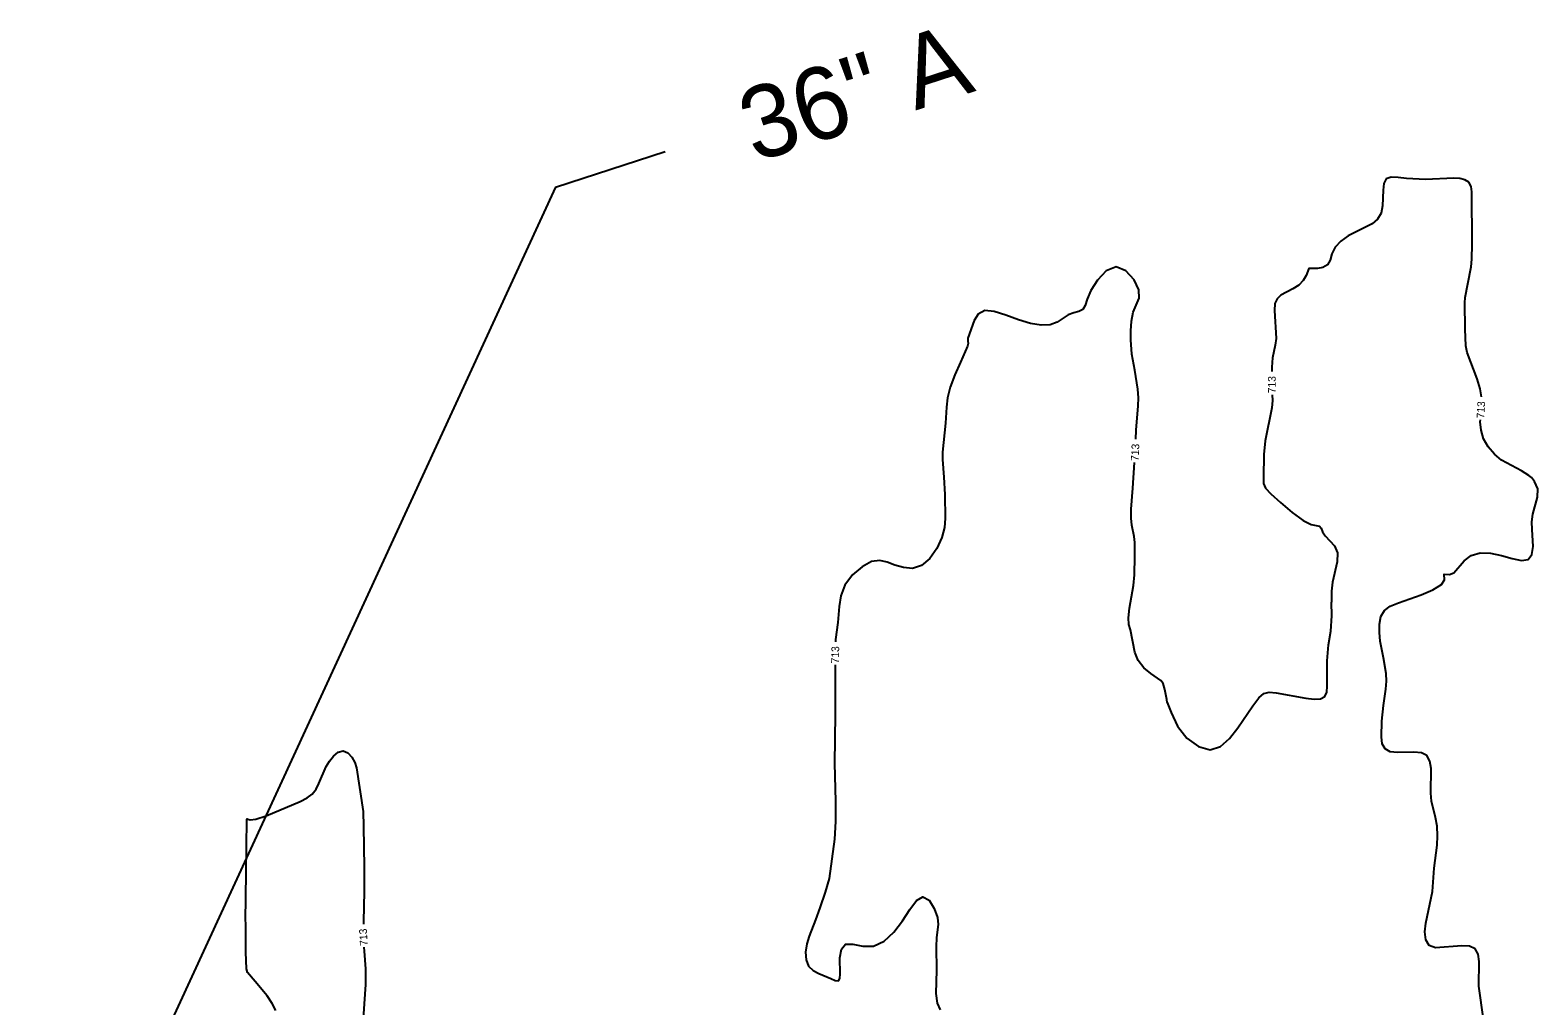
# Model space of a CAD drawing. Extents: x -468548933 to 3387700, y -306089263 to 1207014.
# Drawn here: x 1838088 to 1838869, y 536656 to 537162 of the extents above; entities that cross this region are included whole.
import ezdxf

# ---------------------------------------------------------------- set-up
doc = ezdxf.new("R2010")
doc.units = 0
for name, color, linetype in [('DT_X_Contour_Minor', 7, 'Continuous'), ('Level 19', 7, 'Continuous'), ('Level 40', 7, 'Continuous')]:
    doc.layers.add(name, color=color, linetype=linetype)

msp = doc.modelspace()

# ---------------------------------------------------------------- linework, layer by layer
at = {"layer": 'DT_X_Contour_Minor'}
for points in [[(1838839.34, 536971.92), (1838838.75, 536976.14), (1838837.15, 536981.31), (1838831.89, 536994.94), (1838831.25, 536998.25), (1838830.85, 537006.92), (1838830.82, 537020.53), (1838830.99, 537023.45), (1838832.27, 537030.52), (1838834.02, 537039.35), (1838834.42, 537043.28), (1838834.48, 537050.97), (1838834.37, 537078.09), (1838833.96, 537080.88), (1838832.86, 537083.05), (1838830.82, 537084.39), (1838828.1, 537085.01), (1838825.06, 537085.14), (1838810.3, 537084.43), (1838800.61, 537085.08), (1838796.18, 537085.6), (1838792.52, 537085.71), (1838789.97, 537084.79), (1838788.74, 537082.43), (1838788.4, 537078.97), (1838788.16, 537070.88), (1838787.34, 537067.09), (1838785.61, 537063.93), (1838782.76, 537061.56), (1838770.41, 537055.41), (1838766.48, 537052.64), (1838763.56, 537049.47), (1838761.96, 537046.03), (1838760.98, 537042.79), (1838759.63, 537040.29), (1838757.24, 537038.93), (1838754.38, 537038.42), (1838750, 537038.35), (1838748.5, 537034.72), (1838747.04, 537032.2), (1838744.8, 537029.74), (1838741.76, 537027.79), (1838735.52, 537024.59), (1838733.52, 537022.73), (1838732.44, 537020.22), (1838732.13, 537016.69), (1838733, 537002.19), (1838732.61, 536998.7), (1838731.16, 536992.1), (1838730.77, 536987.33), (1838730.78, 536984.98)], [(1838660.32, 536949.9), (1838660.54, 536954.7), (1838661.62, 536967.33), (1838661.72, 536971.45), (1838661.46, 536975.87), (1838659.78, 536985.71), (1838658.27, 536994.07), (1838657.74, 537001.5), (1838657.71, 537006.18), (1838658.04, 537011.16), (1838659.03, 537015.75), (1838662.11, 537023.07), (1838662, 537027.28), (1838659.52, 537032.51), (1838655.24, 537037.18), (1838650.1, 537039.2), (1838644.96, 537037.17), (1838640.44, 537032.42), (1838637.09, 537026.96), (1838635.21, 537022.47), (1838634.13, 537019.23), (1838632.92, 537017.16), (1838630.89, 537016.09), (1838628.23, 537015.43), (1838625.39, 537014.44), (1838619.7, 537010.67), (1838616.04, 537009.24), (1838611.34, 537009.02), (1838605.74, 537009.94), (1838599.55, 537011.78), (1838593.11, 537014.17), (1838587.08, 537016.14), (1838582.13, 537016.56), (1838578.78, 537014.7), (1838576.7, 537011.43), (1838573.43, 537002.38), (1838573.37, 537000.72), (1838573.58, 536999.53), (1838573.2, 536998.14), (1838569.53, 536989.88), (1838566.69, 536983.38), (1838564.26, 536976.87), (1838562.89, 536971.33), (1838562.33, 536966.63), (1838561.78, 536958.25), (1838560.26, 536943.26), (1838560.22, 536939.36), (1838560.89, 536930.24), (1838561.49, 536921.31), (1838561.65, 536908.82), (1838561.23, 536904.16), (1838559.91, 536898.99), (1838557.35, 536893.36), (1838553.74, 536888.15), (1838549.42, 536884.45), (1838544.72, 536883.04), (1838539.97, 536883.42), (1838535.54, 536884.77), (1838531.61, 536886.27), (1838527.79, 536887.12), (1838523.53, 536886.52), (1838518.55, 536883.91), (1838513.59, 536879.66), (1838509.67, 536874.41), (1838507.5, 536868.76), (1838506.65, 536863.29), (1838506.06, 536854.99), (1838504.84, 536846.15), (1838504.81, 536845.01)], [(1838730.99, 536972.98), (1838731.12, 536969.94), (1838730.76, 536966.25), (1838727.36, 536949.09), (1838726.72, 536942.01), (1838726.42, 536930.13), (1838726.51, 536926.93), (1838727.48, 536924.64), (1838730.22, 536921.71), (1838735.23, 536917.12), (1838741.37, 536911.95), (1838747.11, 536907.81), (1838751.25, 536905.83), (1838755.41, 536904.93), (1838756.28, 536903.84), (1838757.1, 536902.05), (1838758.49, 536899.87), (1838763.26, 536894.66), (1838764.77, 536891.02), (1838764.62, 536886.36), (1838762.23, 536875.91), (1838761.72, 536871.16), (1838761.78, 536865.57)], [(1838865.3, 536930.15), (1838863.89, 536931.22), (1838860.18, 536933.61), (1838849.7, 536939.15), (1838846.13, 536942.17), (1838842.87, 536945.96), (1838840.42, 536950.2), (1838839.13, 536954.61), (1838838.77, 536959.02), (1838838.81, 536959.93)], [(1838676.54, 536813.6), (1838676.4, 536815.05), (1838675.4, 536820.33), (1838674.47, 536823.39), (1838673.26, 536825.01), (1838668.05, 536828.51), (1838664.49, 536831.49), (1838661.52, 536835.27), (1838659.84, 536839.7), (1838657.61, 536851.2), (1838656.79, 536853.98), (1838656.49, 536857.47), (1838657.03, 536862.35), (1838659.09, 536874.17), (1838659.67, 536879.75), (1838659.91, 536889.22), (1838659.79, 536896.53), (1838659.48, 536899.56), (1838658.36, 536905.36), (1838657.98, 536909.02), (1838657.99, 536913.69), (1838658.74, 536924.54), (1838659.72, 536937.91)], [(1838834.03, 536889.78), (1838838.7, 536891.06), (1838844.09, 536890.87), (1838849.76, 536889.7), (1838855.25, 536888.12), (1838860.04, 536887.07), (1838863.56, 536887.56), (1838865.46, 536890.25), (1838866.08, 536894.43), (1838865.65, 536903.24), (1838865.52, 536907.17), (1838866, 536911.17), (1838868.46, 536919.96), (1838868.57, 536924.22), (1838866.85, 536927.99), (1838865.3, 536930.15)], [(1838840.47, 536649.43), (1838838.01, 536666.64), (1838838.18, 536679.38), (1838837.64, 536683.17), (1838836.08, 536685.93), (1838833.2, 536687.27), (1838829.25, 536687.49), (1838815.52, 536686.43), (1838812.23, 536687.65), (1838810.49, 536690.63), (1838810.05, 536694.77), (1838810.51, 536699.23), (1838814.03, 536715.64), (1838814.94, 536727.76), (1838816.46, 536739.62), (1838816.67, 536744.51), (1838816.39, 536749.4), (1838815.53, 536753.97), (1838813.5, 536762.47), (1838813.1, 536766.64), (1838813.24, 536779.41), (1838812.7, 536783.22), (1838811.13, 536786.01), (1838808.25, 536787.4), (1838804.4, 536787.77), (1838795.88, 536787.58), (1838792.17, 536788.03), (1838789.46, 536789.46), (1838788.02, 536792.16), (1838787.57, 536795.8), (1838787.82, 536803.87), (1838788.6, 536811.99), (1838789.86, 536820.48), (1838790.18, 536824.66), (1838790.02, 536828.65), (1838788.66, 536836.63), (1838786.98, 536845.37), (1838786.5, 536849.83), (1838786.52, 536854.16), (1838787.31, 536858.06), (1838789.09, 536861.23), (1838792.09, 536863.49), (1838796.33, 536865.26), (1838808.14, 536869.37), (1838814.24, 536872), (1838818.61, 536874.68), (1838820.28, 536877.14), (1838820.12, 536880.01), (1838822.79, 536879.83), (1838825.06, 536880.73), (1838830.38, 536886.87), (1838834.03, 536889.78)], [(1838676.54, 536813.6), (1838678.6, 536808.29), (1838681.91, 536801.29), (1838686.86, 536795.11), (1838692.78, 536790.72), (1838698.78, 536789.05), (1838704.14, 536790.69), (1838708.89, 536794.86), (1838713.2, 536800.47), (1838720.89, 536811.9), (1838724.05, 536816.04), (1838726.72, 536818.27), (1838729.47, 536818.92), (1838733, 536818.54), (1838748.46, 536815.71), (1838752.81, 536815.27), (1838756.08, 536815.52), (1838758.22, 536816.66), (1838759.25, 536818.86), (1838759.52, 536822), (1838759.44, 536835.17), (1838760.17, 536843.49), (1838761.3, 536850.57), (1838761.91, 536858.49), (1838761.71, 536865.53)], [(1838504.64, 536833.01), (1838504.59, 536807.25), (1838504.24, 536781.88), (1838504.76, 536762.48), (1838504.86, 536751.81), (1838504.24, 536742.69), (1838501.55, 536722.43), (1838499.4, 536715.21), (1838496.77, 536707.21)], [(1838215.02, 536653.97), (1838213.05, 536657.63), (1838210.47, 536661.49), (1838204.29, 536668.95), (1838200.34, 536673.64), (1838199.71, 536675.58), (1838199.44, 536684.12), (1838199.41, 536699.41), (1838199.29, 536700.39), (1838199.58, 536725.05), (1838199.9, 536752.77), (1838200.06, 536753.3), (1838200.41, 536753.07), (1838201.65, 536752.73), (1838204.65, 536753.14), (1838209.89, 536754.91), (1838227.55, 536762.26), (1838231.2, 536764.09), (1838233.86, 536766.12), (1838235.82, 536768.7), (1838237.32, 536771.65), (1838241.09, 536780.36), (1838242.75, 536783.1), (1838244.87, 536785.77), (1838247.3, 536787.8), (1838249.83, 536788.51), (1838252.24, 536787.46), (1838254.31, 536785.17), (1838255.83, 536782.41), (1838256.67, 536779.73), (1838260.23, 536757.11), (1838260.39, 536749.29), (1838260.64, 536728.3), (1838260.77, 536715.67), (1838260.4, 536700.13), (1838260.37, 536698.72)], [(1838496.77, 536707.22), (1838494.51, 536701), (1838491.13, 536692.56), (1838489.94, 536688.51), (1838489.37, 536684.26), (1838489.61, 536680.21), (1838490.86, 536676.88), (1838493.21, 536674.64), (1838496.26, 536673.15), (1838502.38, 536670.57), (1838504.73, 536669.55), (1838506.33, 536669.38), (1838507.07, 536670.52), (1838507.21, 536673), (1838507.11, 536681.34), (1838507.85, 536685.69), (1838509.96, 536688.32), (1838513.85, 536688.38), (1838518.97, 536687.36), (1838524.57, 536687.34), (1838530, 536689.87), (1838535.01, 536694.52), (1838539.49, 536700.35), (1838543.37, 536706.32), (1838546.82, 536711.01), (1838550.08, 536712.91), (1838553.27, 536711.08), (1838555.98, 536706.87), (1838557.68, 536702.2), (1838558.05, 536698.53), (1838557.05, 536691.74), (1838556.93, 536686.95), (1838557.14, 536674.9), (1838556.83, 536662.71), (1838557.44, 536657.86), (1838559.11, 536654.36)], [(1838260.63, 536686.71), (1838260.74, 536684.77), (1838261.48, 536675.63), (1838261.4, 536667.43), (1838259.9, 536644.81)]]:
    msp.add_lwpolyline(points, dxfattribs=at)
at = {"layer": 'Level 40'}
for q in [(1838416.6, 537098.96), (1838087.73, 536489.99)]:
    msp.add_line((1838359.76, 537080.5), q, dxfattribs=at)

# ---------------------------------------------------------------- texts
at = {"layer": 'Level 19'}
for rotation, p in [(90.21221, (1838732.82, 536973.75)), (87.15261, (1838840.85, 536960.6)), (87.3245, (1838661.79, 536938.59)), (88.73398, (1838506.56, 536833.74)), (93.38066, (1838262.58, 536687.6))]:
    msp.add_text('713', height=4, rotation=rotation, dxfattribs=at).set_placement(p)
at = {"layer": 'Level 40'}
msp.add_text('36" A', height=37.5, rotation=17.9864, dxfattribs=at).set_placement((1838462.98, 537093.18))

doc.saveas('drawing.dxf')
